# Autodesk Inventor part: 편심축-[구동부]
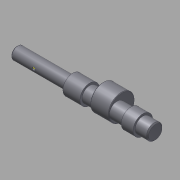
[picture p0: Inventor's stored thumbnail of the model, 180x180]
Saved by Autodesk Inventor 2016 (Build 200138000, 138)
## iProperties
Company: 한국ATC센터
Created: 2015-12
Part Number: 편심축-[구동부]
Document SubType Name: Modeling
Designer: mdu
Density: 7.86 g/cm^3
Mass: 225.292 g
Surface Area: 81.2409 cm^2
Volume: 28.6631 cm^3
Material: 강철, 연강
Appearance: 강철
Author: mdu
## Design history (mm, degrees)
sketch "스케치1"
  geometry: L1 (-86, 0)-(86, 0); L2 (-86, 0)-(-86, 6); L3 (-86, 6)-(-32, 6); L4 (-32, 6)-(-32, 9.5); L5 (-32, 9.5)-(-15.5, 9.5); L6 (-15.5, 9.5)-(-15.5, 7.5); L7 (-15.5, 7.5)-(48, 7.5); L8 (86, 6)-(86, 0); L9 (36, 7.5)-(36, 9.5); L10 (36, 9.5)-(24.5, 9.5); L11 (24.5, 9.5)-(24.5, 7.5); L12 (48, 7.5)-(48, 6); L13 (48, 6)-(86, 6); 2 further points
  constraints: 26 end point, 6 parallel, 6 perpendicular, 2 point on line, 1 coincident, 1 horizontal, 1 midpoint
  dimensions: "d1" = 12 diameter of L3 L1; "d2" = 15 diameter of L7 L1; "d4" = 16.5 distance of L4.end L5.end; "d5" = 19 diameter of L5 L1; "d24" = 11.5 distance of L9.end L10.end; "d25" = 19 diameter of L10 L1; "d27" = 40 distance between parallel lines of L11 L6; "d28" = 54 distance of L2.end L3.end; "d29" = 50 distance between parallel lines of L8 L9; "d41" = 38 distance between parallel lines of L8 L12; "d42" = 12 diameter of L13 L1
revolve "회전1" stored, may be unused: angle "d6" = 90 deg
node "작업 평면1"
sketch "스케치2"
  geometry: C1 r 7.5 at (0, 0) reference; C2 r 12.5 at (0, 4.5); 1 further point
  constraints: 1 centre point, 1 vertical alignment
  dimensions: "d8" = 4.5 distance of point (0, 0) C2.centre; "d9" = 25 diameter of C2
extrude "돌출1" join sketch "스케치2" distance "d10" = 18; taper "d11" = 0 deg
chamfer "모따기1" distance "d12" = 1; stored, may be unused: second distance "d13" = 2, angle "d14" = 45 deg
chamfer "모따기2" distance "d15" = 0.5; stored, may be unused: second distance "d16" = 2, angle "d17" = 45 deg
node "작업 평면2"
sketch "스케치3"
  geometry: L1 (4, -2)-(18, -2); L2 (18, 2)-(4, 2); L3 (27, 5)-(27, -5) reference; A1 r 2 centre (18, 0) between (18, -2) and (18, 2); A2 r 2 centre (4, 0) between (4, 2) and (4, -2); 2 further points
  constraints: 4 end point, 4 point on circle, 4 tangent, 2 centre point, 1 horizontal, 1 horizontal alignment, 1 midpoint, 1 parallel
  dimensions: "d18" = 7 distance edge to line of A1 L3; "d19" = 4 distance between parallel lines of L2 L1; "d20" = 18 dimension on A1 A2
extrude "돌출2" cut sketch "스케치3" distance "d21" = 2.5; taper "d22" = 0 deg
revolve "회전2" stored, may be unused: angle "d26" = 90 deg
node "작업 평면3"
sketch "스케치4"
  geometry: L1 (44, 5)-(44, -5) reference; 2 further points
  constraints: 1 horizontal alignment
  dimensions: "d30" = 12 distance from line of point (32, 0) L1
hole "구멍1" sketch "스케치4" at (32, 0) diameter "d31" = 6; stored, may be unused: countersink angle "d35" = 90 deg, drill point angle "d37" = 118 deg; dims "d32" = 6, "d33" = 14, "d34" = 3, "d36" = 8
node "작업 평면4"
sketch "스케치5"
  geometry: C1 r 3 at (32, 0) reference; C2 r 8 at (32, 0); 2 further points
  constraints: 1 centre point, 1 coincident, 1 other
  dimensions: "d38" = 16 diameter of C2
extrude "돌출3" cut sketch "스케치5" distance "d39" = 3; taper "d40" = 0 deg
sketch "스케치6"
  geometry: L1 (-85, -6)-(-32, -6) reference; L2 (-86, -5)-(-86, 5) reference; L3 (-85, 6)-(-32, 6) reference; L4 (-64, 6)-(-64, -6); L5 (-64, -6)-(-62.5, -6); L6 (-64, -4.5)-(-62.5, -6); L7 (-64, -6)-(-64, -4.5); 2 further points
  constraints: 8 end point, 4 point on line, 2 perpendicular, 1 coincident
  dimensions: "d43" = 22 distance between parallel lines of L4 L2; "d44" = 45 deg angle of L6 L7; "d45" = 3 diameter of L5.end L4
revolve "회전3" stored, may be unused: angle "d46" = 90 deg
node "작업점1"
chamfer "모따기3" distance "d47" = 0.5; stored, may be unused: second distance "d48" = 2, angle "d49" = 45 deg
sketch "스케치7"
  geometry: C1 r 7.5 at (0, 0) reference; 1 further point
extrude "돌출4" cut sketch "스케치7" stored distance "d50" = 10; taper "d51" = 0 deg
chamfer "모따기4" distance "d52" = 1; stored, may be unused: second distance "d53" = 2, angle "d54" = 45 deg
node "작업 평면5"
node "솔리드1"
node "투영된 루프1"
other parameters: "d7" = 8.5
